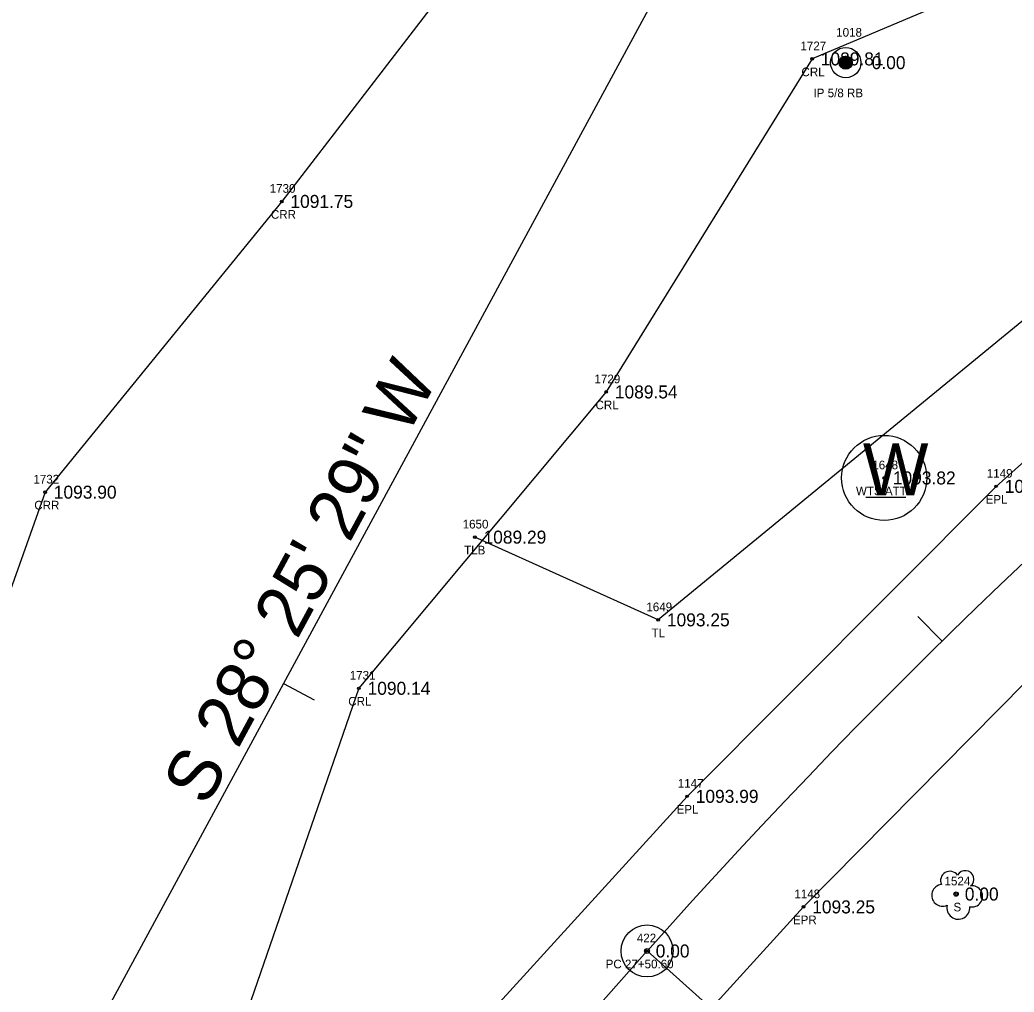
# Model space of a CAD drawing. Extents: x 1539151 to 1541799, y 1198646 to 1201165.
# Drawn here: x 1540728.5 to 1540843.3, y 1200183.3 to 1200295.5 of the extents above; entities that cross this region are included whole.
import ezdxf

# ---------------------------------------------------------------- set-up
doc = ezdxf.new("R2010")
doc.units = 0
for name, color, linetype in [('RD_EX_DV_Prop_txCode', 7, 'Continuous'), ('RD_EX_DV_PropPin', 7, 'Continuous'), ('RD_EX_H2O', 7, 'Continuous'), ('RD_EX_H2O_txCode', 7, 'Continuous'), ('RD_EX_Road', 7, 'Continuous'), ('RD_EX_Road_txCode', 7, 'Continuous'), ('RD_EX_TX_DV_Prop_ELEV', 7, 'Continuous'), ('RD_EX_TX_H2O_ELEV', 7, 'Continuous'), ('RD_EX_TX_Road_ELEV', 7, 'Continuous'), ('RD_EX_TX_UT_ELEV', 7, 'Continuous'), ('RD_EX_TX_VEG_ELEV', 7, 'Continuous'), ('RD_EX_UT', 7, 'Continuous'), ('RD_EX_UT_txCode', 7, 'Continuous'), ('RD_EX_VEG', 7, 'Continuous'), ('RD_EX_VEG_txCode', 7, 'Continuous'), ('RD_HC_Cl', 7, 'Continuous'), ('RD_HC_Data', 7, 'Continuous'), ('RD_HC_Data_Tic', 7, 'Continuous'), ('RD_HC_Survey_ELEV', 7, 'Continuous'), ('RD_HC_txCode', 7, 'Continuous'), ('RD_SMD_Locator', 7, 'Continuous')]:
    doc.layers.add(name, color=color, linetype=linetype)

msp = doc.modelspace()

# ---------------------------------------------------------------- linework, layer by layer
at = {"layer": 'RD_EX_DV_PropPin'}
for p, q in [((1540823.13, 1200290.35), (1540823.13, 1200290.74)), ((1540823.16, 1200290.25), (1540823.16, 1200290.84)), ((1540823.2, 1200290.17), (1540823.2, 1200290.91)), ((1540823.23, 1200290.12), (1540823.23, 1200290.97)), ((1540823.27, 1200290.07), (1540823.27, 1200291.02)), ((1540823.3, 1200290.03), (1540823.3, 1200291.06)), ((1540823.34, 1200289.99), (1540823.34, 1200291.09)), ((1540823.37, 1200289.96), (1540823.37, 1200291.13)), ((1540823.41, 1200289.93), (1540823.41, 1200291.15)), ((1540823.44, 1200289.91), (1540823.44, 1200291.18)), ((1540823.48, 1200289.89), (1540823.48, 1200291.2)), ((1540823.51, 1200289.87), (1540823.51, 1200291.22)), ((1540823.55, 1200289.85), (1540823.55, 1200291.24)), ((1540823.58, 1200289.84), (1540823.58, 1200291.25)), ((1540823.62, 1200289.82), (1540823.62, 1200291.26)), ((1540823.65, 1200289.81), (1540823.65, 1200291.28)), ((1540823.69, 1200289.8), (1540823.69, 1200291.28)), ((1540823.72, 1200289.8), (1540823.72, 1200291.29)), ((1540823.76, 1200289.79), (1540823.76, 1200291.3)), ((1540823.79, 1200289.79), (1540823.79, 1200291.3)), ((1540823.83, 1200289.78), (1540823.83, 1200291.3)), ((1540823.86, 1200289.78), (1540823.86, 1200291.31)), ((1540823.9, 1200289.78), (1540823.9, 1200291.3)), ((1540823.93, 1200289.79), (1540823.93, 1200291.3)), ((1540823.97, 1200289.79), (1540823.97, 1200291.3)), ((1540824, 1200289.8), (1540824, 1200291.29)), ((1540824.04, 1200289.8), (1540824.04, 1200291.28)), ((1540824.07, 1200289.81), (1540824.07, 1200291.28)), ((1540824.11, 1200289.82), (1540824.11, 1200291.26)), ((1540824.14, 1200289.84), (1540824.14, 1200291.25)), ((1540824.18, 1200289.85), (1540824.18, 1200291.24)), ((1540824.21, 1200289.87), (1540824.21, 1200291.22)), ((1540824.25, 1200289.89), (1540824.25, 1200291.2)), ((1540824.28, 1200289.91), (1540824.28, 1200291.18)), ((1540824.32, 1200289.93), (1540824.32, 1200291.15)), ((1540824.35, 1200289.96), (1540824.35, 1200291.13)), ((1540824.39, 1200289.99), (1540824.39, 1200291.09)), ((1540824.42, 1200290.03), (1540824.42, 1200291.06)), ((1540824.46, 1200290.07), (1540824.46, 1200291.02)), ((1540824.49, 1200290.12), (1540824.49, 1200290.97)), ((1540824.53, 1200290.17), (1540824.53, 1200290.91)), ((1540824.56, 1200290.25), (1540824.56, 1200290.84)), ((1540824.6, 1200290.35), (1540824.6, 1200290.74))]:
    msp.add_line(p, q, dxfattribs=at)
for radius in [1.75, 0.761]:
    msp.add_circle((1540823.86, 1200290.54), radius, dxfattribs=at)
at = {"layer": 'RD_EX_H2O'}
for points in [[(1540945.96, 1200515.95), (1540935.66, 1200479.58), (1540934.81, 1200456.33), (1540909.82, 1200438.83), (1540871.91, 1200410.4), (1540829.31, 1200376.16), (1540807.58, 1200340.64), (1540786.11, 1200310.09), (1540758.74, 1200274.52), (1540731.42, 1200240.96), (1540712.61, 1200188.05)], [(1541252.92, 1200441.86), (1541200.84, 1200433.45), (1541140.38, 1200427.39), (1541087.01, 1200428.4), (1541039.74, 1200441.72), (1540997.52, 1200424.93), (1540957.07, 1200418.34), (1540937.15, 1200404.81), (1540902.14, 1200374.36), (1540871.55, 1200334.52), (1540843.47, 1200300.89), (1540819.98, 1200290.97), (1540796.2, 1200252.53), (1540767.65, 1200218.32), (1540745.65, 1200154.73), (1540745.24, 1200145.69), (1540714.12, 1200111.24)]]:
    msp.add_lwpolyline(points, dxfattribs=at)
at = {"layer": 'RD_EX_Road'}
for points in [[(1540705.32, 1200094.04), (1540739.01, 1200131.56), (1540770.5, 1200167.37), (1540805.54, 1200205.85), (1540841.22, 1200241.63), (1540879.37, 1200275.73), (1540919.79, 1200306.26), (1540962.73, 1200334.43), (1541008.04, 1200359.97), (1541051.86, 1200381.29), (1541099.37, 1200400.02), (1541147.99, 1200415.01), (1541197.22, 1200426.76), (1541247.29, 1200435.81)], [(1540718.68, 1200081.33), (1540762.24, 1200130.19), (1540779.72, 1200149.92), (1540818.99, 1200193.09), (1540844.69, 1200219.09), (1540861.59, 1200235.22), (1540891.57, 1200261.37), (1540930.28, 1200290.78), (1540971.82, 1200318.2), (1541015.09, 1200342.79), (1541060.36, 1200364.79), (1541076.53, 1200371.56), (1541099.1, 1200380.09), (1541153.21, 1200396.86), (1541201.21, 1200408.64), (1541249.91, 1200417.32)]]:
    msp.add_lwpolyline(points, dxfattribs=at)
at = {"layer": 'RD_EX_UT'}
msp.add_line((1540826.18, 1200240.39), (1540830.81, 1200240.39), dxfattribs=at)
msp.add_circle((1540828.3, 1200242.6), 4.91, dxfattribs=at)
at = {"layer": 'RD_EX_VEG'}
msp.add_lwpolyline([(1541184.89, 1200430.38), (1541110.91, 1200418.83), (1540957.41, 1200347.72), (1540870.98, 1200282.61), (1540802.21, 1200226.22), (1540781.04, 1200235.77)], dxfattribs=at)
msp.add_circle((1540836.61, 1200194.57), 0.25, dxfattribs=at)
for centre, radius, start, end in [((1540835.89, 1200196.12), 1.08, 34.9763, 204.756), ((1540837.66, 1200196.28), 0.995, 308.7626, 152.0467), ((1540835.05, 1200194.42), 1.26, 96.4518, 294.734), ((1540838.45, 1200194.3), 1.22, 256.5667, 98.1046), ((1540836.86, 1200192.98), 1.32, 166.8827, 5.7589)]:
    msp.add_arc(centre, radius, start, end, dxfattribs=at)
at = {"layer": 'RD_HC_Cl'}
for p, q in [((1540815.59, 1200323.52), (1540714.91, 1200137.52)), ((1540452.58, 1199796.65), (1540800.92, 1200188))]:
    msp.add_line(p, q, dxfattribs=at)
msp.add_arc((1541347.27, 1199701.68), 731.44, 99.31232, 138.32753, dxfattribs=at)
at = {"layer": 'RD_HC_Data'}
msp.add_line((1540800.92, 1200188), (1540888.08, 1200110.41), dxfattribs=at)
for radius in [3, 0.282]:
    msp.add_circle((1540800.92, 1200188), radius, dxfattribs=at)
at = {"layer": 'RD_HC_Data_Tic'}
for p, q in [((1540834.99, 1200223.76), (1540832.19, 1200226.61)), ((1540758.96, 1200218.89), (1540762.47, 1200216.99))]:
    msp.add_line(p, q, dxfattribs=at)
at = {"layer": 'RD_SMD_Locator'}
for centre in [(1540819.98, 1200290.97), (1540823.86, 1200290.54), (1540758.74, 1200274.52), (1540796.2, 1200252.53), (1540828.3, 1200242.6), (1540731.42, 1200240.96), (1540841.22, 1200241.63), (1540781.04, 1200235.77), (1540802.21, 1200226.22), (1540767.65, 1200218.32), (1540805.54, 1200205.85), (1540836.61, 1200194.57), (1540818.99, 1200193.09), (1540800.92, 1200188)]:
    msp.add_circle(centre, 0.15, dxfattribs=at)

# ---------------------------------------------------------------- texts
at = {"layer": 'RD_EX_DV_Prop_txCode'}
for s, p in [('1018', (1540822.76, 1200293.54)), ('IP 5/8 RB', (1540820.14, 1200286.54))]:
    msp.add_text(s, height=1, dxfattribs=at).set_placement(p)
at = {"layer": 'RD_EX_H2O_txCode'}
for s, p in [('1727', (1540818.63, 1200291.97)), ('CRL', (1540818.75, 1200288.97)), ('1730', (1540757.35, 1200275.52)), ('CRR', (1540757.49, 1200272.52)), ('1729', (1540794.85, 1200253.53)), ('CRL', (1540794.97, 1200250.53)), ('1732', (1540730.07, 1200241.96)), ('CRR', (1540730.17, 1200238.96)), ('1731', (1540766.59, 1200219.32)), ('CRL', (1540766.42, 1200216.32))]:
    msp.add_text(s, height=1, dxfattribs=at).set_placement(p)
at = {"layer": 'RD_EX_Road_txCode'}
for s, p in [('1149', (1540840.15, 1200242.63)), ('EPL', (1540840.01, 1200239.63)), ('1147', (1540804.47, 1200206.85)), ('EPL', (1540804.33, 1200203.85)), ('1148', (1540817.93, 1200194.09)), ('EPR', (1540817.76, 1200191.09))]:
    msp.add_text(s, height=1, dxfattribs=at).set_placement(p)
at = {"layer": 'RD_EX_TX_DV_Prop_ELEV'}
msp.add_text('0.00', height=1.5, dxfattribs=at).set_placement((1540826.86, 1200289.79))
at = {"layer": 'RD_EX_TX_H2O_ELEV'}
for s, p in [('1089.81', (1540820.98, 1200290.22)), ('1091.75', (1540759.74, 1200273.77)), ('1089.54', (1540797.2, 1200251.78)), ('1093.90', (1540732.42, 1200240.21)), ('1090.14', (1540768.65, 1200217.57))]:
    msp.add_text(s, height=1.5, dxfattribs=at).set_placement(p)
at = {"layer": 'RD_EX_TX_Road_ELEV'}
for s, p in [('1094.39', (1540842.22, 1200240.88)), ('1093.99', (1540806.54, 1200205.1)), ('1093.25', (1540819.99, 1200192.34))]:
    msp.add_text(s, height=1.5, dxfattribs=at).set_placement(p)
at = {"layer": 'RD_EX_TX_UT_ELEV'}
msp.add_text('1093.82', height=1.5, dxfattribs=at).set_placement((1540829.3, 1200241.85))
at = {"layer": 'RD_EX_TX_VEG_ELEV'}
for s, p in [('1089.29', (1540782.04, 1200235.02)), ('1093.25', (1540803.21, 1200225.47)), ('0.00', (1540837.61, 1200193.82))]:
    msp.add_text(s, height=1.5, dxfattribs=at).set_placement(p)
at = {"layer": 'RD_EX_UT'}
msp.add_text('W', height=6, dxfattribs=at).set_placement((1540825.84, 1200240.6))
at = {"layer": 'RD_EX_UT_txCode'}
for s, p in [('1648', (1540826.93, 1200243.6)), ('WTS ATT', (1540825.04, 1200240.6))]:
    msp.add_text(s, height=1, dxfattribs=at).set_placement(p)
at = {"layer": 'RD_EX_VEG_txCode'}
for s, p in [('1650', (1540779.63, 1200236.77)), ('TLB', (1540779.8, 1200233.77)), ('1649', (1540800.84, 1200227.22)), ('TL', (1540801.44, 1200224.22)), ('1524', (1540835.27, 1200195.57)), ('S', (1540836.3, 1200192.57))]:
    msp.add_text(s, height=1, dxfattribs=at).set_placement(p)
at = {"layer": 'RD_HC_Data'}
msp.add_text('S 28%%d 25\' 29" W', height=6, rotation=61.5754, dxfattribs=at).set_placement((1540750.06, 1200204.55))
at = {"layer": 'RD_HC_Survey_ELEV'}
msp.add_text('0.00', height=1.5, dxfattribs=at).set_placement((1540801.92, 1200187.25))
at = {"layer": 'RD_HC_txCode'}
for s, p in [('422', (1540799.74, 1200189)), ('PC 27+50.60', (1540796.14, 1200186))]:
    msp.add_text(s, height=1, dxfattribs=at).set_placement(p)

doc.saveas('drawing.dxf')
